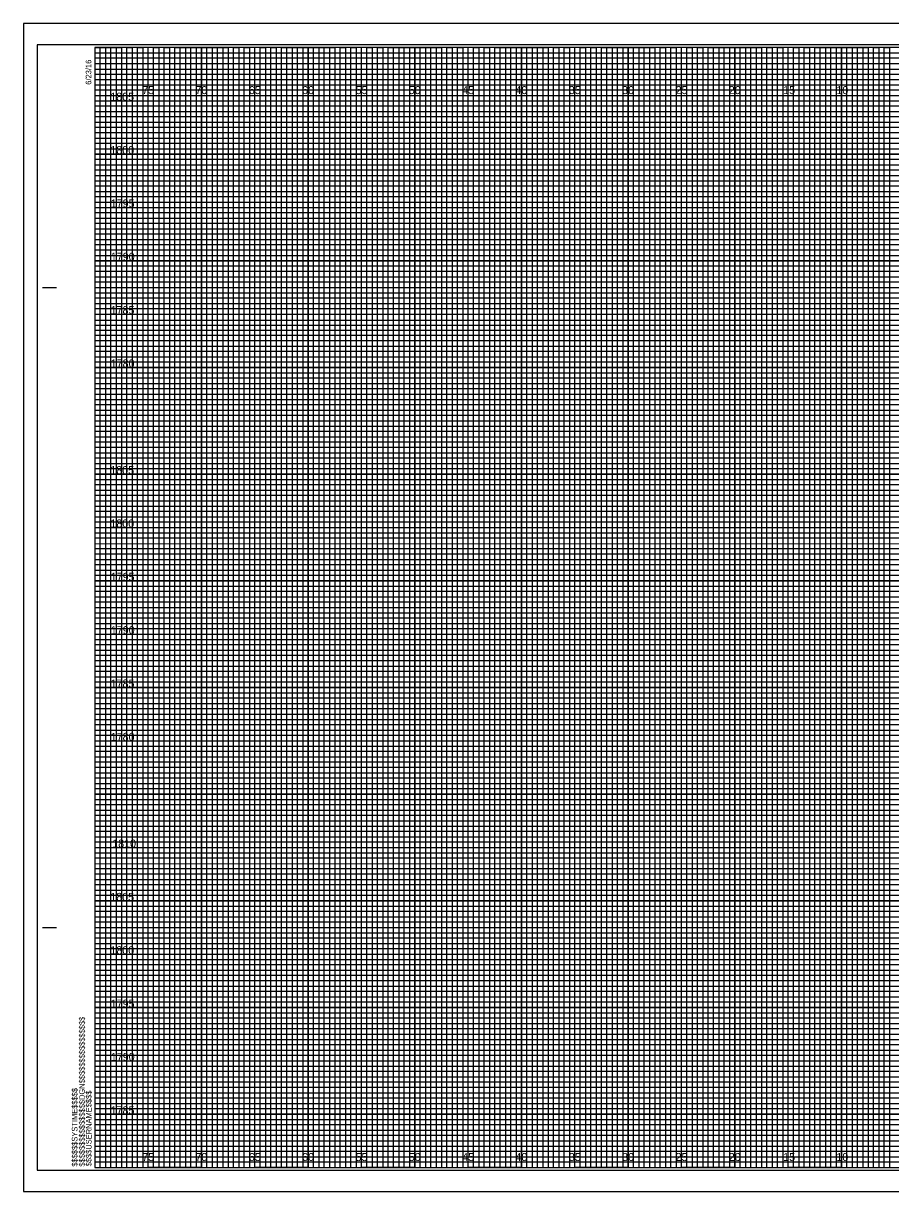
# Model space of a CAD drawing. Extents: x -7 to 162, y -2 to 327.
# Drawn here: x -6.7 to 74.6, y 107.7 to 217.2 of the extents above; entities that cross this region are included whole.
import ezdxf

# ---------------------------------------------------------------- set-up
doc = ezdxf.new("R2010")
doc.units = 0
for name, color, linetype in [('Raster_Level_0', 7, 'Continuous'), ('Scratch_Level_3', 7, 'Continuous'), ('Sheet Cross Section CELL', 7, 'Continuous'), ('Sheet Cross Section Grid Major CELL', 7, 'Continuous'), ('Sheet Cross Section Grid Middle CELL', 7, 'Continuous'), ('Sheet Cross Section Grid Minor 1 CELL', 7, 'Continuous'), ('Sheet Cross Section Grid Minor 2 CELL', 7, 'Continuous'), ('Sheet Cutting Line CELL', 7, 'Continuous'), ('Sheet DOT Grid CELL', 7, 'Continuous'), ('Sheet Plot Border Inside CELL', 7, 'Continuous'), ('Sheet Plot Border Outside CELL', 7, 'Continuous')]:
    doc.layers.add(name, color=color, linetype=linetype)

msp = doc.modelspace()

# ---------------------------------------------------------------- linework, layer by layer
at = {"layer": 'Sheet Cross Section CELL'}
for p, q in [((-4.9, 192.5), (-3.65, 192.5)), ((-4.85, 192.5), (-3.6, 192.5)), ((-4.9, 132.5), (-3.65, 132.5)), ((-4.85, 132.5), (-3.6, 132.5)), ((0, 110), (0, 110)), ((0, 110), (0, 110)), ((0, 110), (0, 110)), ((0, 110), (0, 110)), ((0, 110), (0, 110)), ((0, 110), (0, 110)), ((0, 110), (0, 110))]:
    msp.add_line(p, q, dxfattribs=at)
msp.add_lwpolyline([(160, 215), (0, 215), (0, 110), (160, 110)], close=True, dxfattribs=at)
at = {"layer": 'Sheet Cross Section Grid Major CELL'}
for p, q in [((5, 215), (0, 215)), ((5, 110), (5, 215)), ((15, 215), (10, 215)), ((10, 215), (10, 110)), ((15, 110), (15, 215)), ((25, 215), (20, 215)), ((20, 215), (20, 110)), ((25, 110), (25, 215)), ((35, 215), (30, 215)), ((30, 215), (30, 110)), ((35, 110), (35, 215)), ((45, 215), (40, 215)), ((40, 215), (40, 110)), ((45, 110), (45, 215)), ((55, 215), (50, 215)), ((50, 215), (50, 110)), ((55, 110), (55, 215)), ((65, 215), (60, 215)), ((60, 215), (60, 110)), ((65, 110), (65, 215)), ((75, 215), (70, 215)), ((70, 215), (70, 110)), ((10, 110), (5, 110)), ((20, 110), (15, 110)), ((30, 110), (25, 110)), ((40, 110), (35, 110)), ((50, 110), (45, 110)), ((60, 110), (55, 110)), ((70, 110), (65, 110))]:
    msp.add_line(p, q, dxfattribs=at)
for points in [[(0, 210), (160, 210), (160, 205), (0, 205)], [(0, 200), (160, 200), (160, 195), (0, 195)], [(0, 190), (160, 190), (160, 185), (0, 185)], [(0, 180), (160, 180), (160, 175), (0, 175)], [(0, 170), (160, 170), (160, 165), (0, 165)], [(0, 160), (160, 160), (160, 155), (0, 155)], [(0, 150), (160, 150), (160, 145), (0, 145)], [(0, 140), (160, 140), (160, 135), (0, 135)], [(0, 130), (160, 130), (160, 125), (0, 125)], [(0, 120), (160, 120), (160, 115), (0, 115)]]:
    msp.add_lwpolyline(points, dxfattribs=at)
at = {"layer": 'Sheet Cross Section Grid Middle CELL'}
for points in [[(0, 215), (2.5, 215), (2.5, 110), (7.5, 110), (7.5, 215), (12.5, 215), (12.5, 110), (17.5, 110), (17.5, 215), (22.5, 215), (22.5, 110), (27.5, 110), (27.5, 215), (32.5, 215), (32.5, 110), (37.5, 110), (37.5, 215), (42.5, 215), (42.5, 110), (47.5, 110), (47.5, 215), (52.5, 215), (52.5, 110), (57.5, 110), (57.5, 215), (62.5, 215), (62.5, 110), (67.5, 110), (67.5, 215), (72.5, 215), (72.5, 110), (77.5, 110)], [(0, 212.5), (137.5, 212.5)], [(0, 202.5), (160, 202.5), (160, 207.5), (0, 207.5)], [(0, 192.5), (160, 192.5), (160, 197.5), (0, 197.5)], [(0, 182.5), (160, 182.5), (160, 187.5), (0, 187.5)], [(0, 172.5), (160, 172.5), (160, 177.5), (0, 177.5)], [(0, 162.5), (160, 162.5), (160, 167.5), (0, 167.5)], [(0, 152.5), (160, 152.5), (160, 157.5), (0, 157.5)], [(0, 142.5), (160, 142.5), (160, 147.5), (0, 147.5)], [(0, 132.5), (160, 132.5), (160, 137.5), (0, 137.5)], [(0, 122.5), (160, 122.5), (160, 127.5), (0, 127.5)], [(0, 112.5), (160, 112.5), (160, 117.5), (0, 117.5)]]:
    msp.add_lwpolyline(points, dxfattribs=at)
at = {"layer": 'Sheet Cross Section Grid Minor 1 CELL'}
for p, q in [((0, 214.5), (130, 214.5)), ((130, 213.99), (0, 213.99)), ((0, 213.99), (0, 213.5)), ((0, 213.5), (130, 213.5)), ((130, 212.94), (0, 212.94)), ((0, 212.94), (0, 212)), ((0, 212), (160, 212))]:
    msp.add_line(p, q, dxfattribs=at)
for points in [[(0, 211.5), (135, 211.5), (160, 211.5), (160, 211), (0, 211)], [(0, 210.5), (160, 210.5), (160, 209.5), (0, 209.5)], [(0, 209), (160, 209), (160, 208.5), (0, 208.49)], [(0, 208), (160, 208), (160, 207), (0, 207)], [(0, 206.5), (160, 206.5), (160, 206), (0, 206)], [(0, 205.5), (160, 205.5), (160, 204.5), (0, 204.5)], [(0, 204), (160, 204), (160, 203.5), (0, 203.5)], [(0, 203), (160, 203), (160, 202), (0, 202)], [(0, 201.5), (160, 201.5), (160, 201), (0, 201)], [(0, 200.5), (160, 200.5), (160, 199.5), (0, 199.5)], [(0, 199), (160, 199), (160, 198.5), (0, 198.5)], [(0, 198), (160, 198), (160, 196.97), (160, 196.5), (160, 196), (0, 196)], [(0, 197), (160, 197), (160, 196.5), (0, 196.5)], [(0, 195.5), (160, 195.5), (160, 194.5), (0, 194.52)], [(0, 194.52), (160, 194.5), (160, 194), (0, 194)], [(0, 193.5), (160, 193.5), (160, 193), (0, 193)], [(0, 192), (160, 192), (160, 191.5), (0, 191.5)], [(0, 191), (160, 191), (160, 190.5), (0, 190.5)], [(-0.04, 189.44), (160, 189.44), (160, 188.94), (-0.04, 188.94)], [(0, 188.5), (160, 188.5), (160, 188), (0, 188)], [(0, 187), (160, 187), (160, 186.5), (0, 186.5)], [(0, 186), (160, 186), (160, 185.5), (0, 185.5)], [(0, 184.5), (160, 184.5), (160, 184), (0, 184)], [(0, 183.5), (160, 183.5), (160, 183), (0, 183)], [(0, 182), (160, 182), (160, 181.5), (0, 181.5)], [(0, 181), (160, 181), (160, 180.5), (0, 180.5)], [(0, 179.5), (160, 179.5), (160, 178.99), (0, 179)], [(0, 178.5), (160, 178.5), (160, 178), (0, 178)], [(0, 177), (160, 177), (160, 176.5), (0, 176.5)], [(0, 176), (160, 176), (160, 175.5), (0, 175.5)], [(0, 174.5), (160, 174.5), (160, 174), (0, 174)], [(0, 173.5), (160, 173.5), (160, 173), (0, 173)], [(0, 172), (160, 172), (160, 171.5), (0, 171.5)], [(0, 171), (160, 171), (160, 170.5), (0, 170.5)], [(0, 169.5), (160, 169.5), (160, 169), (0, 169)], [(0, 168.5), (160.03, 168.46), (160, 168), (0, 168)], [(0, 167), (160, 167), (160, 166.5), (0, 166.5)], [(0, 166), (160, 166), (160, 165.5), (0, 165.5)], [(0, 164.5), (160, 164.5), (160, 164), (0, 164)], [(0, 163.5), (160, 163.5), (160, 163), (0, 163)], [(0, 162), (160, 162), (160, 161.5), (0, 161.5)], [(0, 161), (160, 161), (160, 160.5), (0, 160.5)], [(0, 159.5), (160, 159.5), (160, 159), (0, 159)], [(0, 158.5), (160, 158.5), (160, 158), (0, 158)], [(0, 157), (160, 157), (160, 156.5), (0, 156.5)], [(0, 156), (160, 156), (160, 155.5), (0, 155.5)], [(0, 154.5), (160, 154.5), (160, 154), (0, 154)], [(0, 153.5), (160, 153.5), (160, 153), (0, 153)], [(0, 152), (160, 152), (160, 151.5), (0, 151.5)], [(0, 151), (160, 151), (160, 150.5), (0, 150.5)], [(0, 149.5), (160, 149.5), (160, 148.99), (0, 149)], [(0, 148.5), (160, 148.5), (160, 148), (0, 148)], [(0, 147), (160, 147), (160, 146.5), (0, 146.5)], [(0, 146), (160, 146), (160, 145.5), (0, 145.5)], [(0, 144.5), (160, 144.5), (160, 144), (0, 144)], [(0, 143.5), (160, 143.5), (160, 143), (0, 143)], [(0, 142), (160, 142), (160, 141.5), (0, 141.5)], [(0, 141), (160, 141), (160, 140.5), (0, 140.5)], [(0, 139.5), (160, 139.5), (160, 139), (0, 139)], [(0, 138.5), (160.03, 138.46), (160, 138), (0, 138)], [(0, 137), (160, 137), (160, 136.5), (0, 136.5)], [(0, 136), (160, 136), (160, 135.5), (0, 135.5)], [(0, 134.5), (160, 134.5), (160, 134), (0, 134)], [(0, 133.5), (160, 133.5), (160, 133), (0, 133)], [(0, 132), (160, 132), (160, 131.5), (0, 131.5)], [(0, 131), (160, 131), (160, 130.5), (0, 130.5)], [(0, 129.5), (160, 129.5), (160, 129), (0, 129)], [(0, 128.5), (160, 128.5), (160, 128), (0, 128)], [(0, 127), (160, 127), (160, 126.5), (0, 126.5)], [(0, 126), (160, 126), (160, 125.5), (0, 125.5)], [(0, 124.5), (160, 124.5), (160, 124), (0, 124)], [(0, 123.5), (160, 123.5), (160, 123), (0, 123)], [(0, 122), (160, 122), (160, 121.5), (0, 121.5)], [(0, 121), (160, 121), (160, 120.5), (0, 120.5)], [(0, 119.5), (160, 119.5), (160, 119), (0, 119)], [(0, 118.5), (160, 118.5), (160, 118), (0, 118)], [(0, 117), (160, 117), (160, 116.5), (0, 116.5)], [(0, 116), (160, 116), (160, 115.5), (0, 115.5)], [(0, 114.5), (160, 114.5), (160, 114), (0, 114)], [(0, 113.5), (160, 113.5), (160, 113), (0, 113)], [(0, 112), (160, 112), (160, 111.5), (0, 111.5)], [(0, 111), (160, 111), (160, 110.5), (0, 110.5)]]:
    msp.add_lwpolyline(points, dxfattribs=at)
at = {"layer": 'Sheet Cross Section Grid Minor 2 CELL'}
for points in [[(0, 110), (0.5, 110), (0.5, 215), (1, 215), (1, 110)], [(1, 110), (1.5, 110), (1.5, 215), (2, 215), (2, 110)], [(2.5, 110), (3, 110), (3, 215), (3.5, 215), (3.5, 110)], [(3.5, 110), (4, 110), (4, 215), (4.5, 215), (4.5, 110)], [(5, 110), (5.5, 110), (5.5, 215), (6, 215), (6, 110)], [(6, 110), (6.5, 110), (6.5, 215), (7, 215), (7, 110)], [(7.5, 110), (8, 110), (8, 215), (8.5, 215), (8.5, 110)], [(8.5, 110), (9, 110), (9, 215), (9.5, 215), (9.5, 110)], [(10, 110), (10.5, 110), (10.5, 215), (11, 215), (11, 110)], [(11, 110), (11.5, 110), (11.5, 215), (12, 215), (12, 110)], [(12.5, 110), (13, 110), (13, 215), (13.5, 215), (13.5, 110)], [(13.5, 110), (14, 110), (14, 215), (14.5, 215), (14.5, 110)], [(15, 110), (15.5, 110), (15.5, 215), (16, 215), (16, 110)], [(16, 110), (16.5, 110), (16.5, 215), (17, 215), (17, 110)], [(17.5, 110), (18, 110), (18, 215), (18.5, 215), (18.5, 110)], [(18.5, 110), (19, 110), (19, 215), (19.5, 215), (19.5, 110)], [(20, 110), (20.5, 110), (20.5, 215), (21, 215), (21, 110)], [(21, 110), (21.5, 110), (21.5, 215), (22, 215), (22, 110)], [(22.5, 110), (23, 110), (23, 215), (23.5, 215), (23.5, 110)], [(23.5, 110), (24, 110), (24, 215), (24.5, 215), (24.5, 110)], [(25, 110), (25.5, 110), (25.5, 215), (26, 215), (26, 110)], [(26, 110), (26.5, 110), (26.5, 215), (27, 215), (27, 110)], [(27.5, 110), (28, 110), (28, 215), (28.5, 215), (28.5, 110)], [(28.5, 110), (29, 110), (29, 215), (29.5, 215), (29.5, 110)], [(30, 110), (30.5, 110), (30.5, 215), (31, 215), (31, 110)], [(31, 110), (31.5, 110), (31.5, 215), (32, 215), (32, 110)], [(32.5, 110), (33, 110), (33, 215), (33.5, 215), (33.5, 110)], [(33.5, 110), (34, 110), (34, 215), (34.5, 215), (34.5, 110)], [(35, 110), (35.5, 110), (35.5, 215), (36, 215), (36, 110)], [(36, 110), (36.5, 110), (36.5, 215), (37, 215), (37, 110)], [(37.5, 110), (38, 110), (38, 215), (38.5, 215), (38.5, 110)], [(38.5, 110), (39, 110), (39, 215), (39.5, 215), (39.5, 110)], [(40, 110), (40.5, 110), (40.5, 215), (41, 215), (41, 110)], [(41, 110), (41.5, 110), (41.5, 215), (42, 215), (42, 110)], [(42.5, 110), (43, 110), (43, 215), (43.5, 215), (43.5, 110)], [(43.5, 110), (44, 110), (44, 215), (44.5, 215), (44.5, 110)], [(45, 110), (45.5, 110), (45.5, 215), (46, 215), (46, 110)], [(46, 110), (46.5, 110), (46.5, 215), (47, 215), (47, 110)], [(47.5, 110), (48, 110), (48, 215), (48.5, 215), (48.5, 110)], [(48.5, 110), (49, 110), (49, 215), (49.5, 215), (49.5, 110)], [(50, 110), (50.5, 110), (50.5, 215), (51, 215), (51, 110)], [(51, 110), (51.5, 110), (51.5, 215), (52, 215), (52, 110)], [(52.5, 110), (53, 110), (53, 215), (53.5, 215), (53.5, 110)], [(53.5, 110), (54, 110), (54, 215), (54.5, 215), (54.5, 110)], [(55, 110), (55.5, 110), (55.5, 215), (56, 215), (56, 110)], [(56, 110), (56.5, 110), (56.5, 215), (57, 215), (57, 110)], [(57.5, 110), (58, 110), (58, 215), (58.5, 215), (58.5, 110)], [(58.5, 110), (59, 110), (59, 215), (59.5, 215), (59.5, 110)], [(60, 110), (60.5, 110), (60.5, 215), (61, 215), (61, 110)], [(61, 110), (61.5, 110), (61.5, 215), (62, 215), (62, 110)], [(62.5, 110), (63, 110), (63, 215), (63.5, 215), (63.5, 110)], [(63.5, 110), (64, 110), (64, 215), (64.5, 215), (64.5, 110)], [(65, 110), (65.5, 110), (65.5, 215), (66, 215), (66, 110)], [(66, 110), (66.5, 110), (66.5, 215), (67, 215), (67, 110)], [(67.5, 110), (68, 110), (68, 215), (68.5, 215), (68.5, 110)], [(68.5, 110), (69, 110), (69, 215), (69.5, 215), (69.5, 110)], [(70, 110), (70.5, 110), (70.5, 215), (71, 215), (71, 110)], [(71, 110), (71.5, 110), (71.5, 215), (72, 215), (72, 110)], [(72.5, 110), (73, 110), (73, 215), (73.5, 215), (73.5, 110)], [(73.5, 110), (74, 110), (74, 215), (74.5, 215), (74.5, 110)]]:
    msp.add_lwpolyline(points, dxfattribs=at)
at = {"layer": 'Sheet Cutting Line CELL'}
for p, q in [((161.65, 217.25), (-6.7, 217.25)), ((-6.7, 217.25), (-6.7, 107.75)), ((-6.7, 107.75), (161.65, 107.75))]:
    msp.add_line(p, q, dxfattribs=at)
at = {"layer": 'Sheet DOT Grid CELL'}
for p, q in [((5, 110), (5, 215)), ((10, 110), (10, 215)), ((15, 110), (15, 215)), ((20, 110), (20, 215)), ((25, 110), (25, 215)), ((30, 110), (30, 215)), ((35, 110), (35, 215)), ((40, 110), (40, 215)), ((45, 110), (45, 215)), ((50, 110), (50, 215)), ((55, 110), (55, 215)), ((60, 110), (60, 215)), ((65, 110), (65, 215)), ((70, 110), (70, 215)), ((0, 210), (160, 210)), ((0, 205), (160, 205)), ((0, 200), (160, 200)), ((0, 195), (160, 195)), ((0, 190), (160, 190)), ((0, 185), (160, 185)), ((0, 180), (160, 180)), ((0, 175), (160, 175)), ((0, 170), (160, 170)), ((0, 165), (160, 165)), ((0, 160), (160, 160)), ((0, 155), (160, 155)), ((0, 150), (160, 150)), ((0, 145), (160, 145)), ((0, 140), (160, 140)), ((0, 135), (160, 135)), ((0, 130), (160, 130)), ((0, 125), (160, 125)), ((0, 120), (160, 120)), ((0, 115), (160, 115))]:
    msp.add_line(p, q, dxfattribs=at)
at = {"layer": 'Sheet Plot Border Inside CELL'}
msp.add_lwpolyline([(-5.4, 109.75), (161.2, 109.75), (161.2, 215.25), (-5.4, 215.25)], close=True, dxfattribs=at)
at = {"layer": 'Sheet Plot Border Outside CELL'}
msp.add_lwpolyline([(-6.7, 107.75), (161.65, 107.75), (161.65, 217.25), (-6.7, 217.25)], close=True, dxfattribs=at)

# ---------------------------------------------------------------- texts
at = {"layer": 'Raster_Level_0'}
for s, p in [('75', (4.44, 210.62)), ('70', (9.43, 210.62)), ('65', (14.44, 210.62)), ('60', (19.43, 210.62)), ('55', (24.44, 210.62)), ('50', (29.43, 210.62)), ('45', (34.44, 210.62)), ('40', (39.43, 210.62)), ('35', (44.44, 210.62)), ('30', (49.43, 210.62)), ('25', (54.44, 210.62)), ('20', (59.43, 210.62)), ('15', (64.53, 210.62)), ('10', (69.52, 210.62)), ('75', (4.44, 110.62)), ('70', (9.43, 110.62)), ('65', (14.44, 110.62)), ('60', (19.43, 110.62)), ('55', (24.44, 110.62)), ('50', (29.43, 110.62)), ('45', (34.44, 110.62)), ('40', (39.43, 110.62)), ('35', (44.44, 110.62)), ('30', (49.43, 110.62)), ('25', (54.44, 110.62)), ('20', (59.43, 110.62)), ('15', (64.53, 110.62)), ('10', (69.52, 110.62))]:
    msp.add_text(s, height=0.75, dxfattribs=at).set_placement(p)
at = {"layer": 'Scratch_Level_3'}
for s, p in [('1805', (1.45, 210)), ('1800', (1.46, 205)), ('1795', (1.49, 200)), ('1790', (1.5, 195)), ('1785', (1.48, 190)), ('1780', (1.49, 185)), ('1805', (1.45, 175)), ('1800', (1.46, 170)), ('1795', (1.49, 165)), ('1790', (1.5, 160)), ('1785', (1.48, 155)), ('1780', (1.49, 150)), ('1810', (1.63, 140)), ('1805', (1.45, 135)), ('1800', (1.46, 130)), ('1795', (1.49, 125)), ('1790', (1.5, 120)), ('1785', (1.48, 115))]:
    msp.add_text(s, height=0.75, dxfattribs=at).set_placement(p)
at = {"layer": 'Sheet Cross Section CELL'}
for s, p in [('6/23/16', (-0.33, 211.5)), ('$$$$$$$$$$$$$$$$DGN$$$$$$$$$$$$$$$$', (-0.94, 110.09)), ('$$$$$$SYSTIME$$$$$', (-1.63, 110.09)), ('$$$$USERNAME$$$$', (-0.31, 110.12))]:
    msp.add_text(s, height=0.525, rotation=90, dxfattribs=at).set_placement(p)

doc.saveas('drawing.dxf')
